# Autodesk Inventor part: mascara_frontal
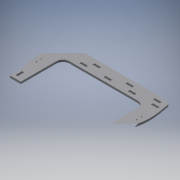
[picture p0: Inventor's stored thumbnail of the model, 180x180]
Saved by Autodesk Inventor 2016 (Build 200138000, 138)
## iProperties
Created: 2017-06
Part Number: mascara_frontal
Material: Generic
Document SubType Name: Modeling
Designer: laboratorioesan
Density: 1 g/cm^3
Appearance: Default
Author: laboratorioesan
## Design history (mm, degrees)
sketch "Sketch1"
  geometry: L1 (280, 0)-(340, 0) reference; L2 (340, 0)-(340, 18.5) reference; L3 (280, 18.5)-(340, 18.5) reference; L4 (280, 0)-(280, 18.5) reference; L5 (70, 0)-(130, 0) reference; L6 (130, 0)-(130, 18.5) reference; L7 (70, 18.5)-(130, 18.5) reference; L8 (70, 0)-(70, 18.5) reference; L9 (500, 0)-(560, 0) reference; L10 (560, 0)-(560, 18.5) reference; L11 (500, 18.5)-(560, 18.5) reference; L12 (500, 0)-(500, 18.5) reference; L13 (720, 0)-(780, 0) reference; L14 (780, 0)-(780, 18.5) reference; L15 (720, 18.5)-(780, 18.5) reference; L16 (720, 0)-(720, 18.5) reference; L17 (930, 0)-(990, 0) reference; L18 (990, 0)-(990, 18.5) reference; L19 (930, 18.5)-(990, 18.5) reference; L20 (930, 0)-(930, 18.5) reference; L21 (0, 0)-(0, 18.5) reference; L22 (130, -432.5)-(130, 0) reference; L23 (111.5, -432.5)-(111.5, 0) reference; L24 (930, -432.5)-(930, 0) reference; L25 (948.5, -432.5)-(948.5, 0) reference; L26 (1060, 0)-(1060, 18.5) reference; L27 (990, 104.496)-(70, 104.496); L28 (70, 104.496)-(0, 0); L29 (0, 0)-(0, -84.685); L30 (57, -270.723)-(130, -270.723); L31 (1060, 0)-(990, 104.496); L32 (130, -270.723)-(160, -270.723); L33 (160, -270.723)-(160, -30); L34 (160, -30)-(900, -30); L35 (900, -30)-(900, -270.723); L36 (900, -270.723)-(1003, -270.723); L37 (1003, -270.723)-(1060, -84.685); L38 (1060, -84.685)-(1060, 0); L39 (0, -84.685)-(57, -270.723)
  constraints: 26 end point, 4 perpendicular, 3 point on line, 2 horizontal, 2 horizontal alignment, 2 vertical, 2 vertical alignment
  dimensions: "d0" = 30 distance of L30.end L32.end; "d1" = 30 distance between parallel lines of L24 L35; "d2" = 30 horizontal distance of L17.start L34.end; "d3" = 70 distance between parallel lines of L29 L8; "d4" = 70 distance between parallel lines of L38 L18 (derived); "d6" = 103 distance of L35.end L36.end; "d7" = 103 distance of L30.start L32.end
extrude "Extrusion1" new body sketch "Sketch1" distance "d8" = 18.5; taper "d9" = 0 deg
fillet "Fillet1" dims "d10" = 60
fillet "Fillet2" dims "d11" = 60
sketch "Sketch2"
  geometry: L1 (930, 0)-(930, 18.5) reference; L2 (930, 18.5)-(990, 18.5) reference; L3 (990, 18.5)-(990, 0) reference; L4 (990, 0)-(930, 0) reference; L5 (720, 0)-(720, 18.5) reference; L6 (720, 18.5)-(780, 18.5) reference; L7 (780, 18.5)-(780, 0) reference; L8 (780, 0)-(720, 0) reference; L9 (500, 0)-(500, 18.5) reference; L10 (500, 18.5)-(560, 18.5) reference; L11 (560, 18.5)-(560, 0) reference; L12 (560, 0)-(500, 0) reference; L13 (70, 0)-(70, 18.5) reference; L14 (70, 18.5)-(130, 18.5) reference; L15 (130, 18.5)-(130, 0) reference; L16 (130, 0)-(70, 0) reference; L17 (280, 0)-(280, 18.5) reference; L18 (280, 18.5)-(340, 18.5) reference; L19 (340, 18.5)-(340, 0) reference; L20 (340, 0)-(280, 0) reference; L21 (52.176, 77.889)-(0, 0) reference; L22 (0, 0)-(0, -84.685) reference; L23 (0, -84.685)-(44.002, -228.3) reference; L24 (101.37, -270.723)-(160, -270.723) reference; L25 (160, -270.723)-(160, -90) reference; L26 (220, -30)-(840, -30) reference; L27 (900, -90)-(900, -270.723) reference; L28 (900, -270.723)-(958.63, -270.723) reference; L29 (1015.998, -228.3)-(1060, -84.685) reference; L30 (1060, -84.685)-(1060, 0) reference; L31 (1060, 0)-(1007.824, 77.889) reference; L32 (957.975, 104.496)-(102.025, 104.496) reference; L33 (960, 67)-(900, 67); L34 (900, 67)-(900, 48.5); L35 (900, 48.5)-(960, 48.5); L36 (960, 48.5)-(960, 67); L37 (710, 48.5)-(650, 48.5); L38 (650, 48.5)-(650, 67); L39 (650, 67)-(710, 67); L40 (710, 67)-(710, 48.5); L41 (410, 48.5)-(350, 48.5); L42 (350, 48.5)-(350, 67); L43 (350, 67)-(410, 67); L44 (410, 67)-(410, 48.5); L45 (160, 48.5)-(100, 48.5); L46 (100, 48.5)-(100, 67); L47 (100, 67)-(160, 67); L48 (160, 67)-(160, 48.5); L49 (948.5, -432.5)-(948.5, 0) reference; L50 (997, -100)-(978.5, -100); L51 (978.5, -100)-(978.5, -40); L52 (978.5, -40)-(997, -40); L53 (997, -40)-(997, -100); L54 (997, -155)-(978.5, -155); L55 (978.5, -155)-(978.5, -215); L56 (978.5, -215)-(997, -215); L57 (997, -215)-(997, -155); L58 (111.5, -432.5)-(111.5, 0) reference; L59 (81.5, -100)-(63, -100); L60 (63, -100)-(63, -40); L61 (63, -40)-(81.5, -40); L62 (81.5, -40)-(81.5, -100); L63 (81.5, -155)-(63, -155); L64 (63, -155)-(63, -215)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; A1 r 60 centre (102.025, 44.496) between (102.025, 104.496) and (52.176, 77.889) reference; A2 r 60 centre (101.37, -210.723) between (44.002, -228.3) and (101.37, -270.723) reference; A3 r 60 centre (220, -90) between (220, -30) and (160, -90) reference; A4 r 60 centre (840, -90) between (900, -90) and (840, -30) reference; A5 r 60 centre (958.63, -210.723) between (958.63, -270.723) and (1015.998, -228.3) reference; A6 r 60 centre (957.975, 44.496) between (1007.824, 77.889) and (957.975, 104.496) reference; 6 further points
  constraints: 64 end point, 16 parallel, 8 horizontal, 8 perpendicular, 7 horizontal alignment, 5 midpoint, 5 point on line, 4 vertical alignment
  dimensions: "d12" = 60 distance of L35.end L34.end; "d13" = 18.5 distance of L34.end L33.end; "d14" = 60 distance of L38.end L39.end; "d15" = 60 distance of L42.end L43.end; "d16" = 60 distance of L46.end L47.end; "d17" = 30 distance from line of L1.end L35; "d18" = 190 distance of L47.end L42.end; "d19" = 190 distance of L37.start L34.end; "d20" = 18.5 distance of L51.end L52.end; "d21" = 60 distance of L50.end L51.end; "d22" = 40 vertical distance of L3.end L52.end; "d23" = 60 distance of L55.end L54.end; "d24" = 30 distance between parallel lines of L49 L51; "d25" = 18.5 distance of L60.end L61.end; "d26" = 60 distance of L64.end L63.end; "d27" = 55 distance of L50.end L54.end; "d28" = 30 distance from line of L58 L59.start
extrude "Extrusion2" cut sketch "Sketch2" distance "d29" = 18.5; taper "d30" = 0 deg
sketch "Sketch3"
  geometry: L1 (81.5, -40)-(81.5, -100) reference; L2 (81.5, -100)-(63, -100) reference; L3 (63, -100)-(63, -40) reference; L4 (63, -40)-(81.5, -40) reference; L5 (997, -40)-(997, -100) reference; L6 (997, -100)-(978.5, -100) reference; L7 (978.5, -100)-(978.5, -40) reference; L8 (978.5, -40)-(997, -40) reference; L9 (410, 67)-(410, 48.5) reference; L10 (410, 48.5)-(350, 48.5) reference; L11 (350, 48.5)-(350, 67) reference; L12 (350, 67)-(410, 67) reference; L13 (900, 48.5)-(900, 67) reference; L14 (900, 67)-(960, 67) reference; L15 (960, 67)-(960, 48.5) reference; L16 (960, 48.5)-(900, 48.5) reference; L17 (710, 67)-(710, 48.5) reference; L18 (710, 48.5)-(650, 48.5) reference; L19 (650, 48.5)-(650, 67) reference; L20 (650, 67)-(710, 67) reference; L21 (160, 67)-(160, 48.5) reference; L22 (160, 48.5)-(100, 48.5) reference; L23 (100, 48.5)-(100, 67) reference; L24 (100, 67)-(160, 67) reference; L25 (978.5, -215)-(978.5, -155) reference; L26 (978.5, -155)-(997, -155) reference; L27 (997, -155)-(997, -215) reference; L28 (997, -215)-(978.5, -215) reference; L29 (63, -215)-(63, -155) reference; L30 (63, -155)-(81.5, -155) reference; L31 (81.5, -155)-(81.5, -215) reference; L32 (81.5, -215)-(63, -215) reference; L33 (930, 0)-(930, 18.5) reference; L34 (930, 18.5)-(990, 18.5) reference; L35 (990, 18.5)-(990, 0) reference; L36 (990, 0)-(930, 0) reference; L37 (720, 0)-(720, 18.5) reference; L38 (720, 18.5)-(780, 18.5) reference; L39 (780, 18.5)-(780, 0) reference; L40 (780, 0)-(720, 0) reference; L41 (500, 0)-(500, 18.5) reference; L42 (500, 18.5)-(560, 18.5) reference; L43 (560, 18.5)-(560, 0) reference; L44 (560, 0)-(500, 0) reference; L45 (70, 0)-(70, 18.5) reference; L46 (70, 18.5)-(130, 18.5) reference; L47 (130, 18.5)-(130, 0) reference; L48 (130, 0)-(70, 0) reference; L49 (280, 0)-(280, 18.5) reference; L50 (280, 18.5)-(340, 18.5) reference; L51 (340, 18.5)-(340, 0) reference; L52 (340, 0)-(280, 0) reference; L53 (52.176, 77.889)-(0, 0) reference; L54 (0, 0)-(0, -84.685) reference; L55 (0, -84.685)-(44.002, -228.3) reference; L56 (101.37, -270.723)-(160, -270.723) reference; L57 (160, -270.723)-(160, -90) reference; L58 (220, -30)-(840, -30) reference; L59 (900, -90)-(900, -270.723) reference; L60 (900, -270.723)-(958.63, -270.723) reference; L61 (1015.998, -228.3)-(1060, -84.685) reference; L62 (1060, -84.685)-(1060, 0) reference; L63 (1060, 0)-(1007.824, 77.889) reference; L64 (957.975, 104.496)-(102.025, 104.496) reference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; A1 r 60 centre (102.025, 44.496) between (102.025, 104.496) and (52.176, 77.889) reference; A2 r 60 centre (101.37, -210.723) between (44.002, -228.3) and (101.37, -270.723) reference; A3 r 60 centre (220, -90) between (220, -30) and (160, -90) reference; A4 r 60 centre (840, -90) between (900, -90) and (840, -30) reference; A5 r 60 centre (958.63, -210.723) between (958.63, -270.723) and (1015.998, -228.3) reference; A6 r 60 centre (957.975, 44.496) between (1007.824, 77.889) and (957.975, 104.496) reference; 1 further point
  constraints: 16 end point, 4 parallel, 2 horizontal, 2 perpendicular
extrude "Extrusion3" join sketch "Sketch3" distance "d31" = 18.5; taper "d32" = 0 deg
sketch "Sketch4"
  geometry: L1 (410, 67)-(410, 48.5) reference; L2 (410, 48.5)-(350, 48.5) reference; L3 (350, 48.5)-(350, 67) reference; L4 (350, 67)-(410, 67) reference; L5 (900, 48.5)-(900, 67) reference; L6 (900, 67)-(960, 67) reference; L7 (960, 67)-(960, 48.5) reference; L8 (960, 48.5)-(900, 48.5) reference; L9 (710, 67)-(710, 48.5) reference; L10 (710, 48.5)-(650, 48.5) reference; L11 (650, 48.5)-(650, 67) reference; L12 (650, 67)-(710, 67) reference; L13 (160, 67)-(160, 48.5) reference; L14 (160, 48.5)-(100, 48.5) reference; L15 (100, 48.5)-(100, 67) reference; L16 (100, 67)-(160, 67) reference; L17 (978.5, -215)-(978.5, -155) reference; L18 (978.5, -155)-(997, -155) reference; L19 (997, -155)-(997, -215) reference; L20 (997, -215)-(978.5, -215) reference; L21 (63, -215)-(63, -155) reference; L22 (63, -155)-(81.5, -155) reference; L23 (81.5, -155)-(81.5, -215) reference; L24 (81.5, -215)-(63, -215) reference; L25 (930, 0)-(930, 18.5) reference; L26 (930, 18.5)-(990, 18.5) reference; L27 (990, 18.5)-(990, 0) reference; L28 (990, 0)-(930, 0) reference; L29 (720, 0)-(720, 18.5) reference; L30 (720, 18.5)-(780, 18.5) reference; L31 (780, 18.5)-(780, 0) reference; L32 (780, 0)-(720, 0) reference; L33 (500, 0)-(500, 18.5) reference; L34 (500, 18.5)-(560, 18.5) reference; L35 (560, 18.5)-(560, 0) reference; L36 (560, 0)-(500, 0) reference; L37 (70, 0)-(70, 18.5) reference; L38 (70, 18.5)-(130, 18.5) reference; L39 (130, 18.5)-(130, 0) reference; L40 (130, 0)-(70, 0) reference; L41 (280, 0)-(280, 18.5) reference; L42 (280, 18.5)-(340, 18.5) reference; L43 (340, 18.5)-(340, 0) reference; L44 (340, 0)-(280, 0) reference; L45 (52.176, 77.889)-(0, 0) reference; L46 (0, 0)-(0, -84.685) reference; L47 (0, -84.685)-(44.002, -228.3) reference; L48 (101.37, -270.723)-(160, -270.723) reference; L49 (160, -270.723)-(160, -90) reference; L50 (220, -30)-(840, -30) reference; L51 (900, -90)-(900, -270.723) reference; L52 (900, -270.723)-(958.63, -270.723) reference; L53 (1015.998, -228.3)-(1060, -84.685) reference; L54 (1060, -84.685)-(1060, 0) reference; L55 (1060, 0)-(1007.824, 77.889) reference; L56 (957.975, 104.496)-(102.025, 104.496) reference; L57 (530, -30)-(530, -112.619); L58 (130, -1020.137)-(130, -1080.137) reference; L59 (130, -1080.137)-(111.5, -1080.137) reference; L60 (111.5, -1080.137)-(111.5, -1020.137) reference; L61 (111.5, -1020.137)-(130, -1020.137) reference; L62 (111.5, -787.5)-(111.5, -769) reference; L63 (111.5, -769)-(150, -769) reference; L64 (150, -769)-(150, -412.5) reference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; C1 r 5.25 at (50, -140); C2 r 5.25 at (1010, -140); A1 r 60 centre (102.025, 44.496) between (102.025, 104.496) and (52.176, 77.889) reference; A2 r 60 centre (101.37, -210.723) between (44.002, -228.3) and (101.37, -270.723) reference; A3 r 60 centre (220, -90) between (220, -30) and (160, -90) reference; A4 r 60 centre (840, -90) between (900, -90) and (840, -30) reference; A5 r 60 centre (958.63, -210.723) between (958.63, -270.723) and (1015.998, -228.3) reference; A6 r 60 centre (957.975, 44.496) between (1007.824, 77.889) and (957.975, 104.496) reference; A7 r 3569.02 centre (-3531.655, -709.325) between (9.303, -1156) and (25, -412.5) reference; A8 r 60 centre (102.025, 44.496) between (102.025, 104.496) and (52.176, 77.889) reference; 1 further point
  constraints: 18 end point, 3 point on line, 2 centre point, 2 parallel, 2 vertical, 1 horizontal, 1 midpoint, 1 perpendicular, 1 symmetric about line, 1 other
  dimensions: "d33" = 10.5 diameter of C1; "d34" = 140 vertical distance of L37.start C1.centre; "d35" = 20 horizontal distance of L37.start C1.centre; "d38" = 18.5 distance of L96.end L95.end; "d39" = 60 distance of L95.end L94.end; "d40" = 15 distance between parallel lines of L74 L97
extrude "Extrusion4" cut sketch "Sketch4" distance "d36" = 18.5; taper "d37" = 0 deg
sketch "Sketch6"
  geometry: L1 (410, 67)-(410, 48.5) reference; L2 (410, 48.5)-(350, 48.5) reference; L3 (350, 48.5)-(350, 67) reference; L4 (350, 67)-(410, 67) reference; L5 (900, 48.5)-(900, 67) reference; L6 (900, 67)-(960, 67) reference; L7 (960, 67)-(960, 48.5) reference; L8 (960, 48.5)-(900, 48.5) reference; L9 (710, 67)-(710, 48.5) reference; L10 (710, 48.5)-(650, 48.5) reference; L11 (650, 48.5)-(650, 67) reference; L12 (650, 67)-(710, 67) reference; L13 (160, 67)-(160, 48.5) reference; L14 (160, 48.5)-(100, 48.5) reference; L15 (100, 48.5)-(100, 67) reference; L16 (100, 67)-(160, 67) reference; L17 (978.5, -215)-(978.5, -155) reference; L18 (978.5, -155)-(997, -155) reference; L19 (997, -155)-(997, -215) reference; L20 (997, -215)-(978.5, -215) reference; L21 (63, -215)-(63, -155) reference; L22 (63, -155)-(81.5, -155) reference; L23 (81.5, -155)-(81.5, -215) reference; L24 (81.5, -215)-(63, -215) reference; L25 (930, 0)-(930, 18.5) reference; L26 (930, 18.5)-(990, 18.5) reference; L27 (990, 18.5)-(990, 0) reference; L28 (990, 0)-(930, 0) reference; L29 (720, 0)-(720, 18.5) reference; L30 (720, 18.5)-(780, 18.5) reference; L31 (780, 18.5)-(780, 0) reference; L32 (780, 0)-(720, 0) reference; L33 (500, 0)-(500, 18.5) reference; L34 (500, 18.5)-(560, 18.5) reference; L35 (560, 18.5)-(560, 0) reference; L36 (560, 0)-(500, 0) reference; L37 (70, 0)-(70, 18.5) reference; L38 (70, 18.5)-(130, 18.5) reference; L39 (130, 18.5)-(130, 0) reference; L40 (130, 0)-(70, 0) reference; L41 (280, 0)-(280, 18.5) reference; L42 (280, 18.5)-(340, 18.5) reference; L43 (340, 18.5)-(340, 0) reference; L44 (340, 0)-(280, 0) reference; L45 (52.176, 77.889)-(0, 0) reference; L46 (0, 0)-(0, -84.685) reference; L47 (0, -84.685)-(44.002, -228.3) reference; L48 (101.37, -270.723)-(160, -270.723) reference; L49 (160, -270.723)-(160, -90) reference; L50 (220, -30)-(840, -30) reference; L51 (900, -90)-(900, -270.723) reference; L52 (900, -270.723)-(958.63, -270.723) reference; L53 (1015.998, -228.3)-(1060, -84.685) reference; L54 (1060, -84.685)-(1060, 0) reference; L55 (1060, 0)-(1007.824, 77.889) reference; L56 (957.975, 104.496)-(102.025, 104.496) reference; L57 (948.5, -432.5)-(948.5, 0) reference; L58 (111.5, -432.5)-(111.5, 0) reference; L59 (1007.824, 77.889)-(1044.661, -134.75); L60 (150, -412.5)-(25, -412.5) reference; L61 (910, -412.5)-(1035, -412.5) reference; L62 (1044.661, -134.75)-(997, -290.306); L63 (1015.998, -228.3)-(1060, -84.685) reference; L64 (997, -290.306)-(997, -412.5)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; C1 r 5.25 at (50, -140) reference; C2 r 5.25 at (1010, -140) reference; C3 r 5.25 at (50, -140); A1 r 60 centre (102.025, 44.496) between (102.025, 104.496) and (52.176, 77.889) reference; A2 r 60 centre (101.37, -210.723) between (44.002, -228.3) and (101.37, -270.723) reference; A3 r 60 centre (220, -90) between (220, -30) and (160, -90) reference; A4 r 60 centre (840, -90) between (900, -90) and (840, -30) reference; A5 r 60 centre (958.63, -210.723) between (958.63, -270.723) and (1015.998, -228.3) reference; A6 r 60 centre (957.975, 44.496) between (1007.824, 77.889) and (957.975, 104.496) reference; A7 r 60 centre (957.975, 44.496) between (1007.824, 77.889) and (957.975, 104.496) reference; A8 r 60 centre (101.37, -210.723) between (44.002, -228.3) and (101.37, -270.723); A9 r 60 centre (102.025, 44.496) between (102.025, 104.496) and (52.176, 77.889); A10 r 60 centre (102.025, 44.496) between (102.025, 104.496) and (52.176, 77.889); 1 further point
  constraints: 34 end point, 8 symmetric about line, 6 point on circle, 5 point on line, 4 centre point, 1 collinear, 1 midpoint, 1 perpendicular, 1 vertical, 4 other
extrude "Extrusion5" cut sketch "Sketch6" distance "d41" = 18.5; taper "d42" = 0 deg
sketch "Sketch7"
  geometry: L1 (280, 0)-(280, 18.5) reference; L2 (280, 18.5)-(340, 18.5) reference; L3 (340, 18.5)-(340, 0) reference; L4 (340, 0)-(280, 0) reference; L5 (70, 0)-(70, 18.5) reference; L6 (70, 18.5)-(130, 18.5) reference; L7 (130, 18.5)-(130, 0) reference; L8 (130, 0)-(70, 0) reference; L9 (500, 0)-(500, 18.5) reference; L10 (500, 18.5)-(560, 18.5) reference; L11 (560, 18.5)-(560, 0) reference; L12 (560, 0)-(500, 0) reference; L13 (720, 0)-(720, 18.5) reference; L14 (720, 18.5)-(780, 18.5) reference; L15 (780, 18.5)-(780, 0) reference; L16 (780, 0)-(720, 0) reference; L17 (930, 0)-(930, 18.5) reference; L18 (930, 18.5)-(990, 18.5) reference; L19 (990, 18.5)-(990, 0) reference; L20 (990, 0)-(930, 0) reference; L21 (63, -215)-(63, -155) reference; L22 (63, -155)-(81.5, -155) reference; L23 (81.5, -155)-(81.5, -215) reference; L24 (81.5, -215)-(63, -215) reference; L25 (978.5, -215)-(978.5, -155) reference; L26 (978.5, -155)-(997, -155) reference; L27 (997, -155)-(997, -215) reference; L28 (997, -215)-(978.5, -215) reference; L29 (160, 67)-(160, 48.5) reference; L30 (160, 48.5)-(100, 48.5) reference; L31 (100, 48.5)-(100, 67) reference; L32 (100, 67)-(160, 67) reference; L33 (710, 67)-(710, 48.5) reference; L34 (710, 48.5)-(650, 48.5) reference; L35 (650, 48.5)-(650, 67) reference; L36 (650, 67)-(710, 67) reference; L37 (900, 48.5)-(900, 67) reference; L38 (900, 67)-(960, 67) reference; L39 (960, 67)-(960, 48.5) reference; L40 (960, 48.5)-(900, 48.5) reference; L41 (410, 67)-(410, 48.5) reference; L42 (410, 48.5)-(350, 48.5) reference; L43 (350, 48.5)-(350, 67) reference; L44 (350, 67)-(410, 67) reference; L45 (1044.661, -134.75)-(1007.824, 77.889) reference; L46 (957.975, 104.496)-(102.025, 104.496) reference; L47 (52.176, 77.889)-(15.339, -134.75) reference; L48 (15.339, -134.75)-(44.002, -228.3) reference; L49 (101.37, -270.723)-(160, -270.723) reference; L50 (160, -270.723)-(160, -90) reference; L51 (220, -30)-(840, -30) reference; L52 (900, -90)-(900, -270.723) reference; L53 (900, -270.723)-(958.63, -270.723) reference; L54 (1015.998, -228.3)-(1044.661, -134.75) reference; L55 (910, -412.5)-(1035, -412.5) reference; L56 (150, -412.5)-(25, -412.5) reference; L57 (900, -90)-(900, -270.723) reference; L58 (900, -270.723)-(900, -412.5); L59 (1040.089, -108.361)-(1045.57, -140); L60 (1045.57, -140)-(997, -298.524); L61 (997, -298.524)-(997, -412.5); L62 (900, -412.5)-(997, -412.5); L63 (18.374, -117.231)-(14.43, -140); L64 (957.975, 104.496)-(102.025, 104.496) reference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; C1 r 5.25 at (1010, -140) reference; C2 r 5.25 at (50, -140) reference; C3 r 5.25 at (50, -140); C4 r 5.25 at (50, -140); A1 r 60 centre (957.975, 44.496) between (1007.824, 77.889) and (957.975, 104.496) reference; A2 r 60 centre (102.025, 44.496) between (102.025, 104.496) and (52.176, 77.889) reference; A3 r 60 centre (101.37, -210.723) between (44.002, -228.3) and (101.37, -270.723) reference; A4 r 60 centre (220, -90) between (220, -30) and (160, -90) reference; A5 r 60 centre (840, -90) between (900, -90) and (840, -30) reference; A6 r 60 centre (958.63, -210.723) between (958.63, -270.723) and (1015.998, -228.3) reference; A7 r 3569.02 centre (-3531.655, -709.325) between (9.303, -1156) and (25, -412.5) reference; A8 r 3569.02 centre (4591.655, -709.325) between (1035, -412.5) and (1050.697, -1156) reference; A9 r 60 centre (101.37, -210.723) between (44.002, -228.3) and (101.37, -270.723); 1 further point
  constraints: 58 end point, 10 symmetric about line, 5 point on line, 3 centre point, 3 parallel, 3 vertical, 2 point on circle, 1 collinear, 1 horizontal, 1 horizontal alignment, 1 midpoint, 1 perpendicular, 2 other
  dimensions: "d43" = 10.5 diameter of C3; "d44" = 60 distance of L80.end L81.end; "d45" = 30 distance between parallel lines of L55 L80; "d46" = 18.5 distance of L80.start L80.end; "d47" = 10 distance between parallel lines of L90 L81
extrude "Extrusion6" join sketch "Sketch7" distance "d48" = 18.5; taper "d49" = 0 deg
sketch "Sketch8"
  geometry: L1 (83, -322.5)-(101.5, -322.5) reference; L2 (101.5, -322.5)-(101.5, -382.5) reference; L3 (101.5, -382.5)-(83, -382.5) reference; L4 (83, -382.5)-(83, -322.5) reference; L5 (977, -322.5)-(977, -382.5) reference; L6 (977, -382.5)-(958.5, -382.5) reference; L7 (958.5, -382.5)-(958.5, -322.5) reference; L8 (958.5, -322.5)-(977, -322.5) reference; L9 (280, 0)-(280, 18.5) reference; L10 (280, 18.5)-(340, 18.5) reference; L11 (340, 18.5)-(340, 0) reference; L12 (340, 0)-(280, 0) reference; L13 (70, 0)-(70, 18.5) reference; L14 (70, 18.5)-(130, 18.5) reference; L15 (130, 18.5)-(130, 0) reference; L16 (130, 0)-(70, 0) reference; L17 (500, 0)-(500, 18.5) reference; L18 (500, 18.5)-(560, 18.5) reference; L19 (560, 18.5)-(560, 0) reference; L20 (560, 0)-(500, 0) reference; L21 (720, 0)-(720, 18.5) reference; L22 (720, 18.5)-(780, 18.5) reference; L23 (780, 18.5)-(780, 0) reference; L24 (780, 0)-(720, 0) reference; L25 (930, 0)-(930, 18.5) reference; L26 (930, 18.5)-(990, 18.5) reference; L27 (990, 18.5)-(990, 0) reference; L28 (990, 0)-(930, 0) reference; L29 (160, 67)-(160, 48.5) reference; L30 (160, 48.5)-(100, 48.5) reference; L31 (100, 48.5)-(100, 67) reference; L32 (100, 67)-(160, 67) reference; L33 (710, 67)-(710, 48.5) reference; L34 (710, 48.5)-(650, 48.5) reference; L35 (650, 48.5)-(650, 67) reference; L36 (650, 67)-(710, 67) reference; L37 (900, 48.5)-(900, 67) reference; L38 (900, 67)-(960, 67) reference; L39 (960, 67)-(960, 48.5) reference; L40 (960, 48.5)-(900, 48.5) reference; L41 (410, 67)-(410, 48.5) reference; L42 (410, 48.5)-(350, 48.5) reference; L43 (350, 48.5)-(350, 67) reference; L44 (350, 67)-(410, 67) reference; L45 (52.176, 77.889)-(14.43, -140) reference; L46 (14.43, -140)-(63, -298.524) reference; L47 (63, -298.524)-(63, -412.5) reference; L48 (63, -412.5)-(160, -412.5) reference; L49 (160, -412.5)-(160, -90) reference; L50 (220, -30)-(840, -30) reference; L51 (900, -90)-(900, -412.5) reference; L52 (900, -412.5)-(997, -412.5) reference; L53 (997, -412.5)-(997, -298.524) reference; L54 (997, -298.524)-(1045.57, -140) reference; L55 (1045.57, -140)-(1007.824, 77.889) reference; L56 (957.975, 104.496)-(102.025, 104.496) reference; C1 r 5.25 at (1010, -140) reference; C2 r 5.25 at (50, -140) reference; C3 r 5.25 at (986, -140); C4 r 5.25 at (74, -140); A1 r 60 centre (220, -90) between (220, -30) and (160, -90) reference; A2 r 60 centre (840, -90) between (900, -90) and (840, -30) reference; A3 r 60 centre (957.975, 44.496) between (1007.824, 77.889) and (957.975, 104.496) reference; A4 r 60 centre (102.025, 44.496) between (102.025, 104.496) and (52.176, 77.889) reference; 1 further point
  constraints: 2 centre point
  dimensions: "d50" = 10.5 diameter of C3; "d51" = 24 distance of C1.centre C3.centre; "d52" = 10.5 diameter of C4; "d53" = 24 distance of C2.centre C4.centre
extrude "Extrusion7" cut sketch "Sketch8" distance "d54" = 18.5; taper "d55" = 0 deg
sketch "Sketch9"
  geometry: L1 (111.5, -432.5)-(111.5, 0) reference; L2 (83, -322.5)-(101.5, -322.5) reference; L3 (101.5, -322.5)-(101.5, -382.5) reference; L4 (101.5, -382.5)-(83, -382.5) reference; L5 (83, -382.5)-(83, -322.5) reference; L6 (977, -322.5)-(977, -382.5) reference; L7 (977, -382.5)-(958.5, -382.5) reference; L8 (958.5, -382.5)-(958.5, -322.5) reference; L9 (958.5, -322.5)-(977, -322.5) reference; L10 (280, 0)-(280, 18.5) reference; L11 (280, 18.5)-(340, 18.5) reference; L12 (340, 18.5)-(340, 0) reference; L13 (340, 0)-(280, 0) reference; L14 (70, 0)-(70, 18.5) reference; L15 (70, 18.5)-(130, 18.5) reference; L16 (130, 18.5)-(130, 0) reference; L17 (130, 0)-(70, 0) reference; L18 (500, 0)-(500, 18.5) reference; L19 (500, 18.5)-(560, 18.5) reference; L20 (560, 18.5)-(560, 0) reference; L21 (560, 0)-(500, 0) reference; L22 (720, 0)-(720, 18.5) reference; L23 (720, 18.5)-(780, 18.5) reference; L24 (780, 18.5)-(780, 0) reference; L25 (780, 0)-(720, 0) reference; L26 (930, 0)-(930, 18.5) reference; L27 (930, 18.5)-(990, 18.5) reference; L28 (990, 18.5)-(990, 0) reference; L29 (990, 0)-(930, 0) reference; L30 (160, 67)-(160, 48.5) reference; L31 (160, 48.5)-(100, 48.5) reference; L32 (100, 48.5)-(100, 67) reference; L33 (100, 67)-(160, 67) reference; L34 (710, 67)-(710, 48.5) reference; L35 (710, 48.5)-(650, 48.5) reference; L36 (650, 48.5)-(650, 67) reference; L37 (650, 67)-(710, 67) reference; L38 (900, 48.5)-(900, 67) reference; L39 (900, 67)-(960, 67) reference; L40 (960, 67)-(960, 48.5) reference; L41 (960, 48.5)-(900, 48.5) reference; L42 (410, 67)-(410, 48.5) reference; L43 (410, 48.5)-(350, 48.5) reference; L44 (350, 48.5)-(350, 67) reference; L45 (350, 67)-(410, 67) reference; L46 (52.176, 77.889)-(14.43, -140) reference; L47 (14.43, -140)-(63, -298.524) reference; L48 (63, -298.524)-(63, -412.5) reference; L49 (63, -412.5)-(160, -412.5) reference; L50 (160, -412.5)-(160, -90) reference; L51 (220, -30)-(840, -30) reference; L52 (900, -90)-(900, -412.5) reference; L53 (900, -412.5)-(997, -412.5) reference; L54 (997, -412.5)-(997, -298.524) reference; L55 (997, -298.524)-(1045.57, -140) reference; L56 (1045.57, -140)-(1007.824, 77.889) reference; L57 (957.975, 104.496)-(102.025, 104.496) reference; C1 r 5.25 at (986, -140) reference; C2 r 5.25 at (74, -140) reference; C3 r 5.25 at (1010, -140) reference; C4 r 5.25 at (50, -140) reference; A1 r 60 centre (220, -90) between (220, -30) and (160, -90) reference; A2 r 60 centre (840, -90) between (900, -90) and (840, -30) reference; A3 r 60 centre (957.975, 44.496) between (1007.824, 77.889) and (957.975, 104.496) reference; A4 r 60 centre (102.025, 44.496) between (102.025, 104.496) and (52.176, 77.889) reference; 1 further point
extrude "Extrusion8" join sketch "Sketch9" distance "d56" = 18.5; taper "d57" = 0 deg
fillet "Fillet3" dims "d58" = 500
sketch "Sketch10"
  geometry: L1 (1037.5, -132.5)-(1056, -132.5) reference; L2 (1056, -132.5)-(1056, -192.5) reference; L3 (1056, -192.5)-(1037.5, -192.5) reference; L4 (1037.5, -192.5)-(1037.5, -132.5) reference; L5 (1002.5, -125.661)-(1027.5, -125.661) reference; L6 (1027.5, -125.661)-(1027.5, -144.161) reference; L7 (1027.5, -144.161)-(1002.5, -144.161) reference; L8 (1002.5, -144.161)-(1002.5, -125.661) reference; L9 (1066, -205)-(1066, -120) reference; L10 (1066, -120)-(1011.617, -120) reference; L11 (1005.816, -165.76)-(1036, -205) reference; L12 (1036, -205)-(1066, -205) reference; L13 (1037.5, -162.5)-(1031.754, -162.5); L14 (957.975, 104.496)-(102.025, 104.496) reference; L15 (530, 104.496)-(530, 58.241); C1 r 5.25 at (986, -140) reference; C2 r 5.25 at (986, -185); C3 r 5.25 at (74, -185); A1 r 32.5 centre (986, -140) between (1011.617, -120) and (1005.816, -165.76) reference; 1 further point
  constraints: 4 end point, 2 centre point, 2 midpoint, 1 horizontal, 1 symmetric about line, 1 vertical, 1 other
  dimensions: "d59" = 10.5 diameter of C2; "d60" = 22.5 vertical distance of L13.start C2.centre
extrude "Extrusion9" cut sketch "Sketch10" distance "d61" = 18.5; taper "d62" = 0 deg
body "Solid1"
node "Reference1"
node "Reference2"
node "Reference3"
node "Reference4"
node "Reference5"
node "Reference6"
node "Reference7"
node "Reference8"
node "Reference9"
node "Reference10"
node "Reference11"
node "Projected Loop1"
node "Reference12"
node "Reference13"
node "Projected Loop2"
node "Projected Loop3"
node "Reference14"
node "Projected Loop4"
node "Reference15"
node "Reference16"
node "Reference17"
node "Reference18"
node "Projected Loop5"
node "Reference19"
node "Reference20"
node "Reference21"
node "Reference22"
node "Reference23"
node "Projected Loop6"
node "Reference24"
node "Projected Loop7"
node "Reference25"
